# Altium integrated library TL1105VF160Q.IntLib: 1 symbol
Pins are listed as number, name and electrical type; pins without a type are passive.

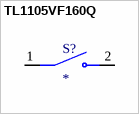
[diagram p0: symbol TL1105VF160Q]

## TL1105VF160Q
designator S?
Tactile Switch, TL1105 Series, SPST-NO, 3.85mm Side Actuated, 0.05A, 12VDC, PC ¦ E-Switch TL1105VF160Q
footprint SW_TL1105VF160Q
pins: 1, 2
